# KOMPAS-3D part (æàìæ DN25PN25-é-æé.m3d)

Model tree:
1. Объединить компоненты:1  (labels: СЕНС DN25PN25-В)
2. Эскиз:1
3. Операция выдавливания:1
     Расстояние 1 = 14
4. Фаска:1
     Угол = 45; Длина 1 = 2; Длина 2 = 2

Referenced files in D:\Савин\!СЕНСОР\3D для заказчика\!Новый перечень\СЕНС\3. СЕНС-В\DN25\: СЕНС DN25PN25-В.a3d
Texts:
  СЕНС DN25PN25-В-СВ
  ООО НПП Сенсор
  СЕНС DN25PN25-В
